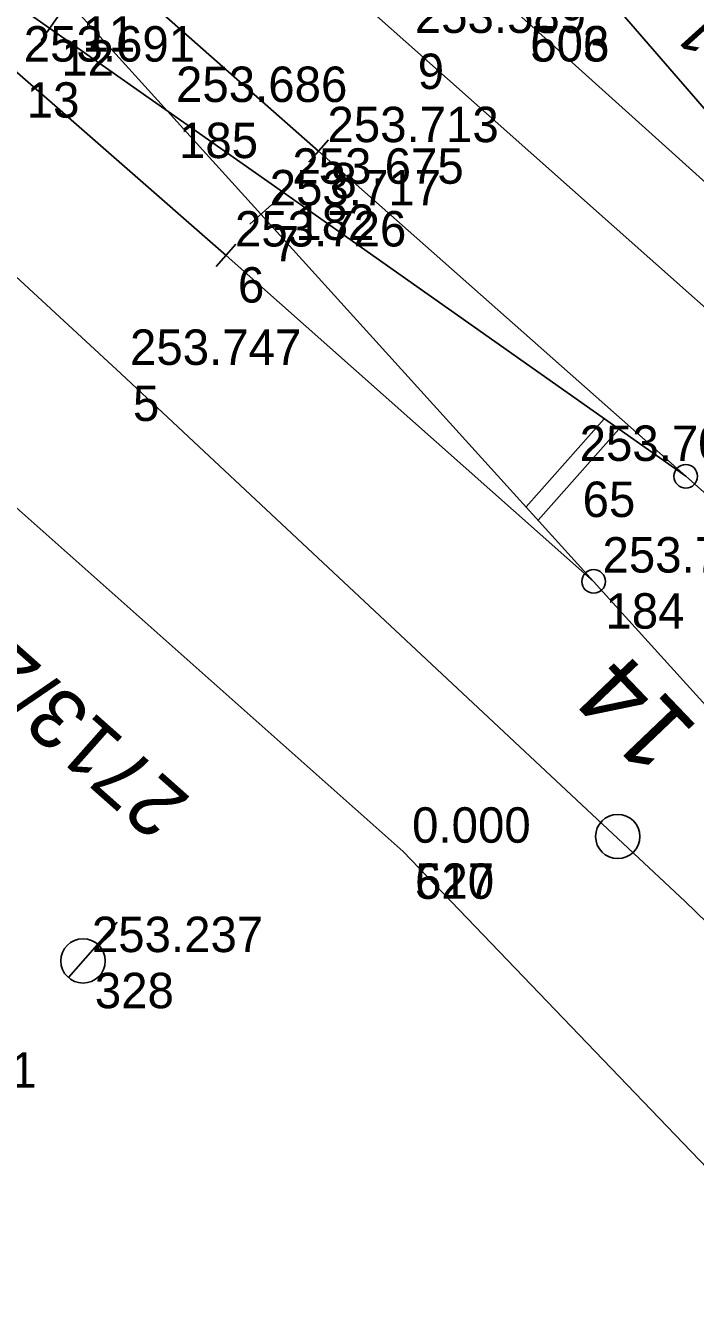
# Model space of a CAD drawing. Extents: x -496688 to -495455, y -1089309 to -1088026.
# Drawn here: x -495926.06 to -495903.37, y -1088706.73 to -1088663.71 of the extents above; entities that cross this region are included whole.
import ezdxf

# ---------------------------------------------------------------- set-up
doc = ezdxf.new("R2010")
doc.units = 0
for name, color, linetype in [('Vrstva 1', 7, 'Continuous'), ('Vrstva 2', 7, 'Continuous'), ('Vrstva 3', 7, 'Continuous'), ('Vrstva 47', 7, 'Continuous'), ('Vrstva 53', 7, 'Continuous'), ('Vrstva 55', 7, 'Continuous'), ('Vrstva 57', 7, 'Continuous'), ('Vrstva 60', 7, 'Continuous'), ('Vrstva 61', 7, 'Continuous'), ('Vrstva 7', 7, 'Continuous')]:
    doc.layers.add(name, color=color, linetype=linetype)

msp = doc.modelspace()

# ---------------------------------------------------------------- linework, layer by layer
at = {"layer": 'Vrstva 1'}
for points in [[(-495794.281, -1088769.662), (-495806.718, -1088758.644), (-495819.114, -1088747.662), (-495828.107, -1088739.648), (-495840.608, -1088728.579), (-495852.984, -1088717.621), (-495860.029, -1088711.42), (-495872.461, -1088700.397), (-495884.955, -1088689.319), (-495893.533, -1088681.721), (-495913.179, -1088664.263), (-495947.105, -1088634.191), (-495952.116, -1088629.76), (-495964.613, -1088618.686), (-495984.901, -1088600.717), (-495997.336, -1088589.715), (-496002.819, -1088584.884), (-496021.751, -1088568.167), (-496024.418, -1088565.811), (-496062.504, -1088532.205), (-496086.773, -1088510.767), (-496106.199, -1088493.629), (-496127.249, -1088474.987), (-496164.633, -1088441.927)], [(-495875.462, -1088716.542), (-495884.273, -1088707.491), (-495892.725, -1088698.131), (-495899.76, -1088690.34), (-495906.824, -1088682.54), (-495918.092, -1088670.104), (-495924.53, -1088662.996), (-495935.688, -1088650.668), (-495946.859, -1088638.317), (-495948.839, -1088636.121), (-495953.409, -1088631.059), (-495964.613, -1088618.686), (-495975.723, -1088606.415), (-495978.55, -1088603.323), (-495987.022, -1088593.978), (-495995.49, -1088584.636), (-496004.032, -1088575.362), (-496012.801, -1088565.84)], [(-495903.705, -1088678.98), (-495917.323, -1088669.371), (-495925.246, -1088663.805), (-495938.946, -1088654.176), (-495952.525, -1088644.634), (-495954.862, -1088642.985), (-495958.022, -1088640.767), (-495972.56, -1088630.52), (-495979.681, -1088625.505), (-495986.807, -1088620.489), (-496002.959, -1088609.142), (-496027.436, -1088591.913), (-496060.399, -1088568.783)], [(-495883.707, -1088687.975), (-495885.058, -1088686.472), (-495891.052, -1088679.853), (-495901.24, -1088668.642), (-495909.888, -1088658.649), (-495924.816, -1088638.862), (-495941.228, -1088612.636)], [(-495906.824, -1088682.54), (-495919.267, -1088671.496), (-495926.418, -1088665.233), (-495938.946, -1088654.176), (-495951.359, -1088643.225), (-495953.413, -1088641.405), (-495980.867, -1088617.126)], [(-495958.584, -1088642.764), (-495956.407, -1088644.707), (-495955.503, -1088645.516), (-495942.191, -1088657.606), (-495922.821, -1088675.506), (-495903.721, -1088693.384), (-495895.286, -1088701.569)], [(-495784.233, -1088784.889), (-495790.007, -1088779.778), (-495797.538, -1088773.109), (-495802.96, -1088768.305), (-495829.435, -1088744.846), (-495841.88, -1088733.81), (-495854.312, -1088722.787), (-495863.196, -1088714.897), (-495875.701, -1088703.825), (-495888.14, -1088692.81), (-495895.834, -1088685.958), (-495903.705, -1088678.98), (-495916.136, -1088667.962), (-495923.285, -1088661.656)]]:
    msp.add_lwpolyline(points, dxfattribs=at)
at = {"layer": 'Vrstva 2'}
for p, q in [((-495925.534, -1088664.214), (-495924.958, -1088663.396)), ((-495916.468, -1088668.336), (-495915.804, -1088667.588)), ((-495917.612, -1088669.779), (-495917.034, -1088668.963)), ((-495918.463, -1088670.44), (-495917.721, -1088669.768)), ((-495919.599, -1088671.87), (-495918.935, -1088671.122))]:
    msp.add_line(p, q, dxfattribs=at)
for points in [[(-495925.246, -1088663.805), (-495938.946, -1088654.176), (-495952.525, -1088644.634)], [(-495895.834, -1088685.958), (-495903.705, -1088678.98), (-495916.136, -1088667.962)], [(-495903.705, -1088678.98), (-495917.323, -1088669.371)], [(-495899.76, -1088690.34), (-495906.824, -1088682.54), (-495918.092, -1088670.104)], [(-495906.824, -1088682.54), (-495919.267, -1088671.496)]]:
    msp.add_lwpolyline(points, dxfattribs=at)
for centre in [(-495903.705, -1088678.98), (-495906.824, -1088682.54)]:
    msp.add_circle(centre, 0.4, dxfattribs=at)
at = {"layer": 'Vrstva 47'}
msp.add_line((-495924.609, -1088695.956), (-495922.951, -1088694.085), dxfattribs=at)
msp.add_circle((-495924.112, -1088695.395), 0.75, dxfattribs=at)
at = {"layer": 'Vrstva 53'}
msp.add_lwpolyline([(-496003.534, -1088369.744), (-496002.28, -1088375.11), (-496002.19, -1088375.66), (-496000.91, -1088380.74), (-496000.83, -1088381.05), (-495997.31, -1088380.16), (-495982.62, -1088436.04), (-495950.27, -1088527.28), (-495948.71, -1088533.28), (-495927, -1088620.27), (-495919.06, -1088642.9), (-495909.37, -1088663.33), (-495876.99, -1088692.49)], dxfattribs=at)
at = {"layer": 'Vrstva 55'}
msp.add_lwpolyline([(-495885.37, -1088726.6), (-495891.03, -1088719.09), (-495893.76, -1088712.02), (-495913.27, -1088691.69), (-495950.46, -1088658.62), (-495980.13, -1088676.15), (-495992.49, -1088666.19), (-496006.16, -1088672.1)], dxfattribs=at)
at = {"layer": 'Vrstva 60'}
for p, q in [((-495925.246, -1088663.805), (-495925.246, -1088663.805)), ((-495925.246, -1088663.805), (-495925.246, -1088663.805)), ((-495913.179, -1088664.263), (-495913.179, -1088664.263)), ((-495913.179, -1088664.263), (-495913.179, -1088664.263)), ((-495921.263, -1088666.602), (-495921.263, -1088666.602)), ((-495921.263, -1088666.602), (-495921.263, -1088666.602)), ((-495916.136, -1088667.962), (-495916.136, -1088667.962)), ((-495916.136, -1088667.962), (-495916.136, -1088667.962)), ((-495917.323, -1088669.371), (-495917.323, -1088669.371)), ((-495917.323, -1088669.371), (-495917.323, -1088669.371)), ((-495918.092, -1088670.104), (-495918.092, -1088670.104)), ((-495918.092, -1088670.104), (-495918.092, -1088670.104)), ((-495919.267, -1088671.496), (-495919.267, -1088671.496)), ((-495919.267, -1088671.496), (-495919.267, -1088671.496)), ((-495922.821, -1088675.506), (-495922.821, -1088675.506)), ((-495922.821, -1088675.506), (-495922.821, -1088675.506)), ((-495907.598, -1088678.759), (-495907.598, -1088678.759)), ((-495907.598, -1088678.759), (-495907.598, -1088678.759)), ((-495903.705, -1088678.98), (-495903.705, -1088678.98)), ((-495903.705, -1088678.98), (-495903.705, -1088678.98)), ((-495906.824, -1088682.54), (-495906.824, -1088682.54)), ((-495906.824, -1088682.54), (-495906.824, -1088682.54)), ((-495913.27, -1088691.69), (-495913.27, -1088691.69)), ((-495913.27, -1088691.69), (-495913.27, -1088691.69)), ((-495903.721, -1088693.384), (-495903.721, -1088693.384)), ((-495903.721, -1088693.384), (-495903.721, -1088693.384)), ((-495924.112, -1088695.395), (-495924.112, -1088695.395)), ((-495924.112, -1088695.395), (-495924.112, -1088695.395))]:
    msp.add_line(p, q, dxfattribs=at)
at = {"layer": 'Vrstva 7'}
for p, q in [((-495906.468, -1088677.03), (-495909.111, -1088680.016)), ((-495905.975, -1088677.378), (-495908.706, -1088680.463))]:
    msp.add_line(p, q, dxfattribs=at)
msp.add_circle((-495906.009, -1088691.18), 0.75, dxfattribs=at)

# ---------------------------------------------------------------- texts
at = {"layer": 'Vrstva 2'}
msp.add_text('14', height=2.5, rotation=133.6913, dxfattribs=at).set_placement((-495903.228, -1088687.538))
at = {"layer": 'Vrstva 3'}
msp.add_text('Vk.1', height=1.5, rotation=132.043, dxfattribs=at).set_placement((-495900.371, -1088666.033))
at = {"layer": 'Vrstva 57'}
msp.add_text('2713/2', height=2, rotation=138.4565, dxfattribs=at).set_placement((-495920.413, -1088689.913))
at = {"layer": 'Vrstva 60'}
for s, p in [('11', (-495924.13, -1088664.596)), ('11', (-495924.13, -1088664.596)), ('503', (-495908.97, -1088664.93)), ('606', (-495908.97, -1088664.93)), ('12', (-495924.846, -1088665.405)), ('12', (-495924.846, -1088665.405)), ('9', (-495912.779, -1088665.863)), ('9', (-495912.779, -1088665.863)), ('13', (-495926.018, -1088666.833)), ('13', (-495926.018, -1088666.833)), ('185', (-495920.863, -1088668.202)), ('185', (-495920.863, -1088668.202)), ('8', (-495915.736, -1088669.562)), ('8', (-495915.736, -1088669.562)), ('182', (-495916.923, -1088670.971)), ('182', (-495916.923, -1088670.971)), ('7', (-495917.692, -1088671.704)), ('7', (-495917.692, -1088671.704)), ('6', (-495918.867, -1088673.096)), ('6', (-495918.867, -1088673.096)), ('5', (-495922.421, -1088677.106)), ('5', (-495922.421, -1088677.106)), ('65', (-495907.198, -1088680.359)), ('65', (-495907.198, -1088680.359)), ('184', (-495906.424, -1088684.14)), ('184', (-495906.424, -1088684.14)), ('517', (-495912.87, -1088693.29)), ('620', (-495912.87, -1088693.29)), ('328', (-495923.712, -1088696.995)), ('328', (-495923.712, -1088696.995))]:
    msp.add_text(s, height=1.2, dxfattribs=at).set_placement(p)
at = {"layer": 'Vrstva 61'}
for s, p in [('253.589', (-495912.879, -1088663.963)), ('253.589', (-495912.879, -1088663.963)), ('253.691', (-495926.118, -1088664.933)), ('253.691', (-495926.118, -1088664.933)), ('253.686', (-495920.963, -1088666.302)), ('253.686', (-495920.963, -1088666.302)), ('253.713', (-495915.836, -1088667.662)), ('253.713', (-495915.836, -1088667.662)), ('253.675', (-495917.023, -1088669.071)), ('253.675', (-495917.023, -1088669.071)), ('253.717', (-495917.792, -1088669.804)), ('253.717', (-495917.792, -1088669.804)), ('253.726', (-495918.967, -1088671.196)), ('253.726', (-495918.967, -1088671.196)), ('253.747', (-495922.521, -1088675.206)), ('253.747', (-495922.521, -1088675.206)), ('253.708', (-495907.298, -1088678.459)), ('253.708', (-495907.298, -1088678.459)), ('253.796', (-495906.524, -1088682.24)), ('253.796', (-495906.524, -1088682.24)), ('0.000', (-495912.97, -1088691.39)), ('0.000', (-495912.97, -1088691.39)), ('253.237', (-495923.812, -1088695.095)), ('253.237', (-495923.812, -1088695.095)), ('253.481', (-495931.483, -1088699.69)), ('253.481', (-495931.483, -1088699.69))]:
    msp.add_text(s, height=1.2, dxfattribs=at).set_placement(p)

doc.saveas('drawing.dxf')
